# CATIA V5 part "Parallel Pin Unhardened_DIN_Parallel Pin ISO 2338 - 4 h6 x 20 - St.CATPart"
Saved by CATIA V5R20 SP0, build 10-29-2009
Part number: Parallel Pin Unhardened_DIN_Parallel Pin ISO 2338 - 4 h6 x 20 - St
Revision: ANY
Definition: UNKNOWN
Nomenclature: Parallel Pin Unhardened_DIN_Parallel Pin ISO 2338 - 4 h6 x 20 - St
Source: Unknown
Bounding box of the stored display mesh (mm): x 0 to 20, y -2 to 2, z -2 to 2
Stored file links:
  C:\Users\Utente\Desktop\IO LAVORO\3D X SITO CF\CUMSA\3D files SD\SD 3220\Parallel Pin Unhardened_DIN_Parallel Pin ISO 2338 - 4 h6 x 20 - St.CATPart
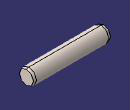
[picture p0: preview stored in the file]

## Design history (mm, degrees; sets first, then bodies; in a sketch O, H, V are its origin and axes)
Body1 "Base-Revolve" (main body)
  Solid1: solid without history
